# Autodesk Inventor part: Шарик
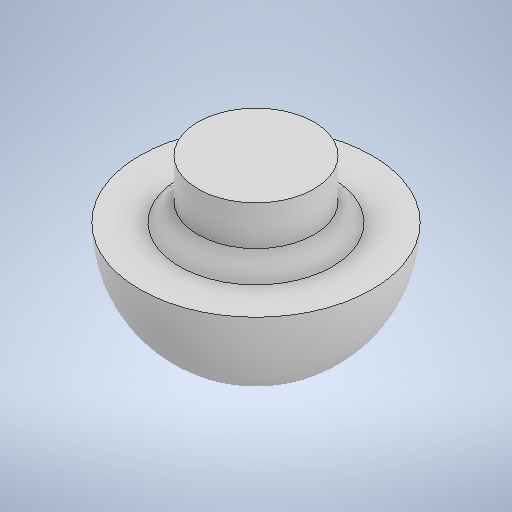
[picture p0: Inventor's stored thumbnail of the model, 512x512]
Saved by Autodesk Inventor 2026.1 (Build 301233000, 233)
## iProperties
Created: 2026-01
Part Number: Шарик
Material: Типовые
Document SubType Name: Modeling
Designer: Yury Melnikov
Density: 1 g/cm^3
Appearance: По умолчанию
Author: Yury Melnikov
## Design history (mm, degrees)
sketch "Эскиз1"
  geometry: L1 (-1.671, 0)-(1.622, 0); L2 (-1.671, 0.1)-(1.622, 0.1); L3 (0, 1.711)-(0, -1.41); L4 (-0.6, 0.1)-(-0.6, 0.5); L5 (-0.6, 0.5)-(0, 0.5); C1 r 1 at (0, 0); 4 further points
  constraints: 10 end point, 4 point on line, 2 vertical, 1 centre point, 1 coincident, 1 horizontal, 1 midpoint, 1 parallel, 1 perpendicular
  dimensions: "d0" = 2 diameter of C1; "d1" = 0.1 distance between parallel lines of L1 L2; "d2" = 0.4 distance of L4.start L4.end; "d3" = 1.2 diameter of point (-0.6, 0.3) L3
revolve "Вращение1" sketch "Эскиз1" stored, may be unused: angle "d4" = 90 deg
chamfer "Фаска1" distance "d5" = 0.1; stored, may be unused: second distance "d6" = 2, angle "d7" = 45 deg
sketch "Эскиз2"
  geometry: L1 (2.343, 0)-(-1.397, 0); C1 r 1 at (0, 0); A1 r 1 centre (0, 0) between (0.1, -0.995) and (0.1, 0.995) reference; 3 further points
  constraints: 2 end point, 1 centre point, 1 coincident, 1 concentric, 1 horizontal
revolve "Вращение2" sketch "Эскиз2" stored, may be unused: angle "d8" = 90 deg
feature "Комбинировать1"
feature "Толщина1" dims "d9" = 0.1, "d10" = 0.1
sketch "Эскиз3"
  geometry: C1 r 2.447 at (0, 0); C2 r 0.822 at (0, 0); 1 further point
  constraints: 2 centre point, 2 coincident
extrude "Выдавливание1" cut sketch "Эскиз3" distance "d11" = 10; taper "d12" = 0 deg
node "Твердое тело1"
node "Твердое тело2"
